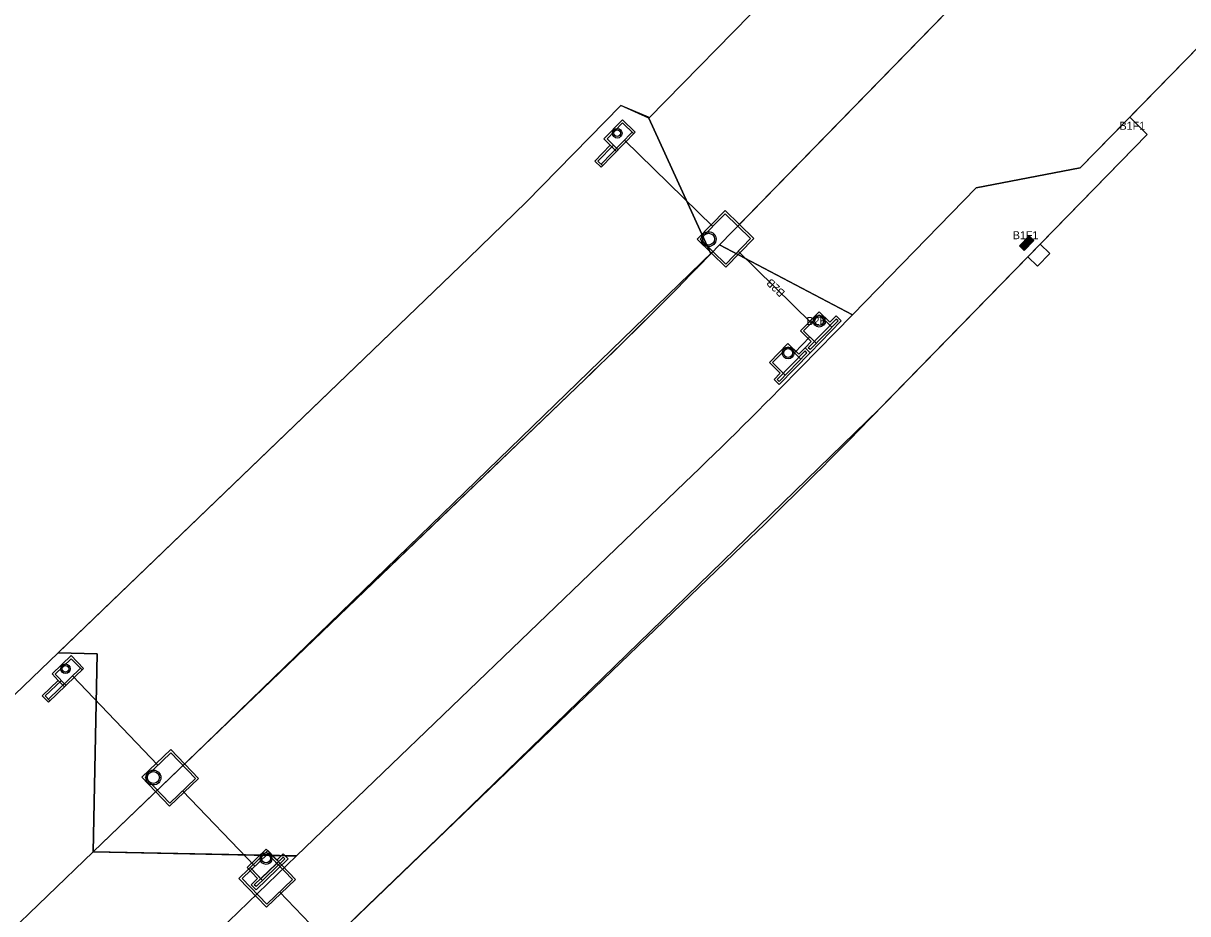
# Model space of a CAD drawing. Extents: x 2251012 to 2259557, y 13786786 to 13792525.
# Drawn here: x 2255240.9 to 2255502.9, y 13791117.1 to 13791317.3 of the extents above; entities that cross this region are included whole.
import ezdxf

# ---------------------------------------------------------------- set-up
doc = ezdxf.new("R2010")
doc.units = 0
for name, color, linetype in [('D_BOXES_1', 7, 'Continuous'), ('D_DRAIN_MISC', 7, 'Continuous'), ('D_DRAIN_NOTES_1', 7, 'Continuous'), ('D_DRN_AREA_B', 7, 'Continuous'), ('D_DRN_AREA_X', 7, 'Continuous'), ('D_INLET_1', 7, 'Continuous'), ('D_PIPES_1', 7, 'Continuous'), ('D_RDWY_CONC_RIPRAP', 7, 'Continuous')]:
    doc.layers.add(name, color=color, linetype=linetype)

msp = doc.modelspace()

# ---------------------------------------------------------------- linework, layer by layer
at = {"layer": 'D_BOXES_1'}
for p, q in [((2255520.53, 13791393.48), (2255401.66, 13791271.67)), ((2255396.07, 13791265.95), (2255276.86, 13791150.44)), ((2255276.74, 13791144.78), (2255293.02, 13791127.83)), ((2255298.56, 13791122.06), (2255309.3, 13791110.88))]:
    msp.add_line(p, q, dxfattribs=at)
at = {"layer": 'D_DRAIN_MISC'}
for p, q in [((2255373.99, 13791293.08), (2255373.99, 13791293.08)), ((2255375.07, 13791292.03), (2255375.07, 13791292.03)), ((2255376.81, 13791293.82), (2255376.81, 13791293.82)), ((2255373.32, 13791290.24), (2255373.32, 13791290.24)), ((2255376.14, 13791290.98), (2255376.14, 13791290.98)), ((2255396, 13791271.6), (2255396, 13791271.6)), ((2255401.66, 13791271.67), (2255401.66, 13791271.67)), ((2255398.86, 13791268.81), (2255398.86, 13791268.81)), ((2255396.07, 13791265.95), (2255396.07, 13791265.95)), ((2255401.73, 13791266.02), (2255401.73, 13791266.02)), ((2255418.19, 13791249.95), (2255418.19, 13791249.95)), ((2255421.36, 13791250.34), (2255421.36, 13791250.34)), ((2255419.62, 13791248.56), (2255419.62, 13791248.56)), ((2255421.05, 13791247.16), (2255421.05, 13791247.16)), ((2255417.87, 13791246.77), (2255417.87, 13791246.77)), ((2255411.2, 13791242.8), (2255411.2, 13791242.8)), ((2255414.38, 13791243.19), (2255414.38, 13791243.19)), ((2255410.89, 13791239.61), (2255410.89, 13791239.61)), ((2255412.63, 13791241.4), (2255412.63, 13791241.4)), ((2255414.07, 13791240), (2255414.07, 13791240)), ((2255249.9, 13791172.73), (2255249.9, 13791172.73)), ((2255250.94, 13791171.65), (2255250.94, 13791171.65)), ((2255252.74, 13791173.38), (2255252.74, 13791173.38)), ((2255249.14, 13791169.92), (2255249.14, 13791169.92)), ((2255251.98, 13791170.57), (2255251.98, 13791170.57)), ((2255271.2, 13791150.55), (2255271.2, 13791150.55)), ((2255276.86, 13791150.44), (2255276.86, 13791150.44)), ((2255273.97, 13791147.67), (2255273.97, 13791147.67)), ((2255271.09, 13791144.9), (2255271.09, 13791144.9)), ((2255276.74, 13791144.78), (2255276.74, 13791144.78)), ((2255293.76, 13791129.23), (2255293.76, 13791129.23)), ((2255296.94, 13791129.52), (2255296.94, 13791129.52)), ((2255293.02, 13791127.83), (2255293.02, 13791127.83)), ((2255295.14, 13791127.79), (2255295.14, 13791127.79)), ((2255295.14, 13791127.79), (2255295.14, 13791127.79)), ((2255298.68, 13791127.72), (2255298.68, 13791127.72)), ((2255293.34, 13791126.06), (2255293.34, 13791126.06)), ((2255296.53, 13791126.35), (2255296.53, 13791126.35)), ((2255292.91, 13791122.18), (2255292.91, 13791122.18)), ((2255298.56, 13791122.06), (2255298.56, 13791122.06))]:
    msp.add_line(p, q, dxfattribs=at)
at = {"layer": 'D_DRN_AREA_B'}
for p, q in [((2255489.83, 13791296.17), (2255707.42, 13791519.14)), ((2255472.95, 13791389.15), (2255381.67, 13791295.92)), ((2255375.34, 13791298.76), (2255354.02, 13791277.09)), ((2255381.67, 13791295.92), (2255375.34, 13791298.76)), ((2255493.75, 13791292.31), (2255489.83, 13791296.17)), ((2255433.37, 13791230.43), (2255493.75, 13791292.31)), ((2255354.02, 13791277.09), (2255341.17, 13791264.54)), ((2255341.17, 13791264.54), (2255248.73, 13791175.76)), ((2255336.23, 13791136.05), (2255433.37, 13791230.43)), ((2255248.73, 13791175.76), (2255226.58, 13791154.5)), ((2255318.46, 13791118.99), (2255336.23, 13791136.05)), ((2255288.25, 13791089.98), (2255318.46, 13791118.99))]:
    msp.add_line(p, q, dxfattribs=at)
at = {"layer": 'D_DRN_AREA_X'}
for p, q in [((2255683.04, 13791560.02), (2255397.55, 13791267.46)), ((2255478.69, 13791284.75), (2255707.42, 13791519.14)), ((2255472.95, 13791389.15), (2255381.67, 13791295.92)), ((2255375.34, 13791298.76), (2255354.02, 13791277.09)), ((2255381.56, 13791296.18), (2255375.34, 13791298.76)), ((2255381.67, 13791295.92), (2255381.56, 13791296.18)), ((2255395.6, 13791265.47), (2255381.67, 13791295.92)), ((2255381.67, 13791295.92), (2255395.6, 13791265.47)), ((2255491.61, 13791294.41), (2255489.83, 13791296.17)), ((2255493.75, 13791292.31), (2255491.61, 13791294.41)), ((2255428.73, 13791225.69), (2255493.75, 13791292.31)), ((2255455.25, 13791280.3), (2255478.69, 13791284.75)), ((2255455.25, 13791280.3), (2255427.42, 13791251.78)), ((2255427.42, 13791251.78), (2255455.25, 13791280.3)), ((2255354.02, 13791277.09), (2255341.17, 13791264.54)), ((2255392.67, 13791262.46), (2255395.6, 13791265.47)), ((2255395.6, 13791265.47), (2255392.67, 13791262.46)), ((2255397.55, 13791267.46), (2255395.6, 13791265.47)), ((2255427.42, 13791251.78), (2255397.55, 13791267.46)), ((2255397.55, 13791267.46), (2255427.42, 13791251.78)), ((2255341.17, 13791264.54), (2255249.13, 13791176.15)), ((2255427.42, 13791251.78), (2255415.82, 13791239.89)), ((2255415.82, 13791239.89), (2255427.42, 13791251.78)), ((2255427.42, 13791251.78), (2255427.42, 13791251.78)), ((2255427.42, 13791251.78), (2255427.42, 13791251.78)), ((2255256.66, 13791131.05), (2255367.32, 13791237.32)), ((2255389.76, 13791214.04), (2255302.38, 13791130.12)), ((2255302.38, 13791130.12), (2255389.76, 13791214.04)), ((2255288.25, 13791089.98), (2255402.69, 13791199.88)), ((2255248.73, 13791175.76), (2255226.58, 13791154.5)), ((2255249.13, 13791176.15), (2255248.73, 13791175.76)), ((2255248.73, 13791175.76), (2255257.56, 13791175.58)), ((2255257.56, 13791175.58), (2255248.73, 13791175.76)), ((2255257.56, 13791175.58), (2255256.66, 13791131.05)), ((2255256.66, 13791131.05), (2255257.56, 13791175.58)), ((2255256.66, 13791131.05), (2255062.92, 13790944.99)), ((2255062.92, 13790944.99), (2255256.66, 13791131.05)), ((2255302.38, 13791130.12), (2255256.66, 13791131.05)), ((2255274.73, 13791103.57), (2255302.38, 13791130.12)), ((2255302.38, 13791130.12), (2255274.73, 13791103.57)), ((2255300.49, 13791130.16), (2255302.38, 13791130.12)), ((2255302.38, 13791130.12), (2255302.38, 13791130.12)), ((2255302.38, 13791130.12), (2255302.38, 13791130.12))]:
    msp.add_line(p, q, dxfattribs=at)
for points in [[(2255395.6, 13791265.47), (2255397.55, 13791267.46), (2255683.04, 13791560.02)], [(2255489.83, 13791296.17), (2255478.69, 13791284.75), (2255455.25, 13791280.3)], [(2255367.32, 13791237.32), (2255320.85, 13791192.69), (2255256.66, 13791131.05)], [(2255256.66, 13791131.05), (2255300.08, 13791130.17), (2255300.49, 13791130.16)]]:
    msp.add_lwpolyline(points, dxfattribs=at)
for centre, radius, start, end in [((2254605.4, 13792030.71), 1100, 313.84074, 315.70035), ((2254605.4, 13792030.71), 1100, 313.84074, 315.69373), ((2254605.4, 13792030.71), 1100, 315.69373, 315.70035), ((2254606.36, 13792029.79), 1131, 313.84074, 315.70035), ((2254606.36, 13792029.79), 1131, 313.84074, 315.70035), ((2254593.41, 13792042.58), 1168.37, 313.84074, 315.63907)]:
    msp.add_arc(centre, radius, start, end, dxfattribs=at)
at = {"layer": 'D_INLET_1'}
for p, q in [((2255371.54, 13791291.28), (2255375.73, 13791295.58)), ((2255372.25, 13791291.29), (2255375.74, 13791294.87)), ((2255375.73, 13791295.58), (2255378.59, 13791292.78)), ((2255375.74, 13791294.87), (2255378.24, 13791292.42)), ((2255370.9, 13791285.62), (2255377.89, 13791292.77)), ((2255370.91, 13791284.91), (2255378.59, 13791292.78)), ((2255369.48, 13791286.31), (2255372.97, 13791289.88)), ((2255370.19, 13791286.31), (2255373.68, 13791289.89)), ((2255371.54, 13791291.28), (2255372.97, 13791289.88)), ((2255372.25, 13791291.29), (2255374.75, 13791288.85)), ((2255372.97, 13791289.88), (2255374.4, 13791288.49)), ((2255369.48, 13791286.31), (2255370.91, 13791284.91)), ((2255370.19, 13791286.31), (2255371.26, 13791285.27)), ((2255392.5, 13791268.73), (2255398.79, 13791275.17)), ((2255393.21, 13791268.74), (2255398.79, 13791274.47)), ((2255398.79, 13791275.17), (2255405.23, 13791268.89)), ((2255398.79, 13791274.47), (2255404.52, 13791268.88)), ((2255398.94, 13791262.45), (2255392.5, 13791268.73)), ((2255398.93, 13791263.15), (2255393.21, 13791268.74)), ((2255404.52, 13791268.88), (2255398.93, 13791263.15)), ((2255405.23, 13791268.89), (2255398.94, 13791262.45)), ((2255465, 13791267.23), (2255467.19, 13791269.47)), ((2255465.21, 13791267.17), (2255467.26, 13791269.27)), ((2255465.52, 13791266.72), (2255467.71, 13791268.96)), ((2255465.98, 13791266.42), (2255468.03, 13791268.52)), ((2255466.03, 13791268), (2255466.79, 13791267.25)), ((2255466.05, 13791266.21), (2255468.23, 13791268.46)), ((2255466.1, 13791268.35), (2255467.14, 13791267.33)), ((2255466.14, 13791268.12), (2255466.91, 13791267.37)), ((2255466.18, 13791268.16), (2255466.95, 13791267.41)), ((2255466.29, 13791268.27), (2255467.06, 13791267.53)), ((2255466.33, 13791268.31), (2255467.09, 13791267.56)), ((2255466.44, 13791268.43), (2255467.21, 13791267.68)), ((2255466.48, 13791268.47), (2255467.25, 13791267.72)), ((2255466.6, 13791268.59), (2255467.36, 13791267.84)), ((2255466.63, 13791268.63), (2255467.4, 13791267.88)), ((2255466.75, 13791268.74), (2255467.52, 13791268)), ((2255466.79, 13791268.78), (2255467.55, 13791268.03)), ((2255466.9, 13791268.9), (2255467.67, 13791268.15)), ((2255466.94, 13791268.94), (2255467.71, 13791268.19)), ((2255467.05, 13791269.06), (2255467.82, 13791268.31)), ((2255467.09, 13791269.1), (2255467.86, 13791268.35)), ((2255467.19, 13791269.47), (2255468.23, 13791268.46)), ((2255467.21, 13791269.21), (2255467.98, 13791268.47)), ((2255467.24, 13791269.25), (2255468.01, 13791268.5)), ((2255467.26, 13791269.27), (2255468.03, 13791268.52)), ((2255467.64, 13791268.89), (2255467.64, 13791268.89)), ((2255465, 13791267.23), (2255466.05, 13791266.21)), ((2255465.21, 13791267.17), (2255465.98, 13791266.42)), ((2255465.22, 13791267.18), (2255465.99, 13791266.43)), ((2255465.26, 13791267.22), (2255466.03, 13791266.47)), ((2255465.38, 13791267.34), (2255466.14, 13791266.59)), ((2255465.41, 13791267.38), (2255466.18, 13791266.63)), ((2255465.53, 13791267.49), (2255466.3, 13791266.75)), ((2255465.57, 13791267.53), (2255466.33, 13791266.78)), ((2255465.59, 13791266.79), (2255465.59, 13791266.79)), ((2255465.68, 13791267.65), (2255466.45, 13791266.9)), ((2255465.72, 13791267.69), (2255466.49, 13791266.94)), ((2255465.84, 13791267.81), (2255466.6, 13791267.06)), ((2255465.87, 13791267.85), (2255466.64, 13791267.1)), ((2255465.99, 13791267.97), (2255466.76, 13791267.22)), ((2255466.62, 13791267.84), (2255466.62, 13791267.84)), ((2255419.92, 13791252.45), (2255415.73, 13791248.15)), ((2255419.92, 13791252.45), (2255422.37, 13791250.06)), ((2255419.93, 13791251.74), (2255416.44, 13791248.16)), ((2255423.78, 13791250.78), (2255417.49, 13791244.34)), ((2255424.19, 13791250.38), (2255417.91, 13791243.94)), ((2255424.9, 13791250.39), (2255417.92, 13791243.23)), ((2255419.93, 13791251.74), (2255422.8, 13791248.95)), ((2255423.77, 13791251.49), (2255422.37, 13791250.06)), ((2255424.9, 13791250.39), (2255423.77, 13791251.49)), ((2255424.19, 13791250.38), (2255423.78, 13791250.78)), ((2255415.73, 13791248.15), (2255418.18, 13791245.77)), ((2255416.44, 13791248.16), (2255419.3, 13791245.37)), ((2255412.94, 13791245.29), (2255408.75, 13791241)), ((2255412.95, 13791244.58), (2255409.46, 13791241.01)), ((2255412.94, 13791245.29), (2255415.39, 13791242.9)), ((2255412.95, 13791244.58), (2255415.81, 13791241.79)), ((2255418.18, 13791245.77), (2255416.79, 13791244.33)), ((2255416.79, 13791243.63), (2255410.51, 13791237.19)), ((2255417.21, 13791243.22), (2255410.92, 13791236.78)), ((2255417.92, 13791243.23), (2255410.93, 13791236.07)), ((2255416.79, 13791244.33), (2255415.39, 13791242.9)), ((2255417.92, 13791243.23), (2255416.79, 13791244.33)), ((2255417.92, 13791243.23), (2255416.79, 13791244.33)), ((2255417.21, 13791243.22), (2255416.79, 13791243.63)), ((2255417.91, 13791243.94), (2255417.49, 13791244.34)), ((2255408.75, 13791241), (2255411.2, 13791238.61)), ((2255409.46, 13791241.01), (2255412.32, 13791238.21)), ((2255411.2, 13791238.61), (2255409.8, 13791237.18)), ((2255410.93, 13791236.07), (2255409.8, 13791237.18)), ((2255410.92, 13791236.78), (2255410.51, 13791237.19)), ((2255247.39, 13791171.02), (2255251.72, 13791175.17)), ((2255248.1, 13791171), (2255251.7, 13791174.46)), ((2255251.7, 13791174.46), (2255254.13, 13791171.94)), ((2255251.72, 13791175.17), (2255254.49, 13791172.29)), ((2255246.56, 13791164.67), (2255254.49, 13791172.29)), ((2255246.57, 13791165.37), (2255253.78, 13791172.3)), ((2255245.17, 13791166.11), (2255248.78, 13791169.57)), ((2255245.88, 13791166.1), (2255249.48, 13791169.56)), ((2255247.39, 13791171.02), (2255248.78, 13791169.57)), ((2255248.1, 13791171), (2255250.52, 13791168.48)), ((2255248.78, 13791169.57), (2255250.16, 13791168.13)), ((2255245.17, 13791166.11), (2255246.56, 13791164.67)), ((2255245.88, 13791166.1), (2255246.92, 13791165.01)), ((2255267.61, 13791147.8), (2255274.1, 13791154.03)), ((2255268.32, 13791147.78), (2255274.09, 13791153.32)), ((2255274.09, 13791153.32), (2255279.63, 13791147.55)), ((2255274.1, 13791154.03), (2255280.33, 13791147.54)), ((2255273.84, 13791141.31), (2255267.61, 13791147.8)), ((2255273.86, 13791142.01), (2255268.32, 13791147.78)), ((2255280.33, 13791147.54), (2255273.84, 13791141.31)), ((2255279.63, 13791147.55), (2255273.86, 13791142.01)), ((2255289.43, 13791125.08), (2255295.92, 13791131.31)), ((2255290.13, 13791125.06), (2255295.9, 13791130.61)), ((2255295.57, 13791131.67), (2255291.25, 13791127.52)), ((2255295.56, 13791130.97), (2255291.95, 13791127.5)), ((2255299.37, 13791129.88), (2255292.88, 13791123.65)), ((2255300.48, 13791129.45), (2255293.27, 13791122.53)), ((2255299.77, 13791129.47), (2255293.28, 13791123.23)), ((2255295.56, 13791130.97), (2255298.33, 13791128.08)), ((2255295.57, 13791131.67), (2255297.94, 13791129.21)), ((2255295.9, 13791130.61), (2255301.45, 13791124.83)), ((2255295.92, 13791131.31), (2255302.15, 13791124.82)), ((2255299.38, 13791130.59), (2255297.94, 13791129.21)), ((2255299.77, 13791129.47), (2255299.37, 13791129.88)), ((2255300.48, 13791129.45), (2255299.38, 13791130.59)), ((2255291.25, 13791127.52), (2255293.61, 13791125.05)), ((2255291.95, 13791127.5), (2255294.72, 13791124.62)), ((2255292.3, 13791127.14), (2255294.38, 13791124.98)), ((2255294.38, 13791124.98), (2255297.98, 13791128.44)), ((2255295.66, 13791118.59), (2255289.43, 13791125.08)), ((2255295.68, 13791119.29), (2255290.13, 13791125.06)), ((2255293.61, 13791125.05), (2255292.17, 13791123.66)), ((2255302.15, 13791124.82), (2255295.66, 13791118.59)), ((2255301.45, 13791124.83), (2255295.68, 13791119.29)), ((2255293.27, 13791122.53), (2255292.17, 13791123.66)), ((2255293.28, 13791123.23), (2255292.88, 13791123.65))]:
    msp.add_line(p, q, dxfattribs=at)
for centre, radius in [((2255374.53, 13791292.56), 1.08), ((2255374.53, 13791292.56), 0.75), ((2255395.09, 13791268.76), 1.67), ((2255395.09, 13791268.76), 1.33), ((2255466.62, 13791267.84), 0.303), ((2255466.62, 13791267.84), 0.25), ((2255419.95, 13791250.33), 1.33), ((2255419.95, 13791250.33), 1), ((2255412.97, 13791243.17), 1.33), ((2255412.97, 13791243.17), 1), ((2255250.42, 13791172.19), 1.08), ((2255250.42, 13791172.19), 0.75), ((2255270.2, 13791147.75), 1.67), ((2255270.2, 13791147.75), 1.33), ((2255295.53, 13791129.55), 1.33), ((2255295.53, 13791129.55), 1)]:
    msp.add_circle(centre, radius, dxfattribs=at)
at = {"layer": 'D_PIPES_1'}
for p, q in [((2255376.14, 13791290.98), (2255396, 13791271.6)), ((2255418.19, 13791249.95), (2255401.73, 13791266.02)), ((2255414.38, 13791243.19), (2255417.87, 13791246.77)), ((2255251.98, 13791170.57), (2255271.2, 13791150.55))]:
    msp.add_line(p, q, dxfattribs=at)
at = {"layer": 'D_RDWY_CONC_RIPRAP'}
for p, q in [((2255469.68, 13791267.64), (2255466.89, 13791264.78)), ((2255469.05, 13791262.67), (2255471.84, 13791265.54)), ((2255471.84, 13791265.54), (2255469.68, 13791267.64)), ((2255466.89, 13791264.78), (2255469.05, 13791262.67))]:
    msp.add_line(p, q, dxfattribs=at)

# ---------------------------------------------------------------- texts
at = {"layer": 'D_DRAIN_NOTES_1'}
for s, p in [('B1F1', (2255487.52, 13791293.34)), ('B1F1', (2255463.51, 13791268.74)), ('B2B', (2255417.08, 13791249.46))]:
    msp.add_text(s, height=1.8, dxfattribs=at).set_placement(p)
msp.add_text('B2B', height=1.8, rotation=135.7003, dxfattribs=at).set_placement((2255412.4, 13791256.86))

doc.saveas('drawing.dxf')
